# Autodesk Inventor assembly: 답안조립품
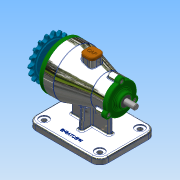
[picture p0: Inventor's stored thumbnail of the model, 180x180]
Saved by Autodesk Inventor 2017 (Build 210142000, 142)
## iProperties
Part Number: 답안조립품
Material: 일반
Document SubType Name: Assembly
Designer: user
Author: user
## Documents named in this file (16)
- C:\Users\user\Desktop\711006V1004\답안조립품.iam
- C:\Users\user\Desktop\711006V1004\본체.ipt
- C:\Users\user\Desktop\711006V1004\앞커버.ipt
- C:\Users\user\Desktop\711006V1004\뒤커버.ipt
- C:\Users\user\Desktop\711006V1004\오일 실 10x20x7.ipt
- C:\Users\user\Desktop\711006V1004\오일 실 17x30x8.ipt
- C:\Users\user\Desktop\711006V1004\베어링 6203.ipt
- C:\Users\user\Desktop\711006V1004\베어링 6200.ipt
- C:\Users\user\Desktop\711006V1004\축.ipt
- C:\Users\user\Desktop\711006V1004\키 5x5.ipt
- 키 5 x 5.ipt
- C:\Users\user\Desktop\711006V1004\와셔.ipt
- C:\Users\user\Desktop\711006V1004\스프로킷.ipt
- C:\Users\user\Desktop\711006V1004\볼트 M4.ipt
- 볼트 M4 x 12.ipt
- C:\Users\user\Desktop\711006V1004\마개.ipt
